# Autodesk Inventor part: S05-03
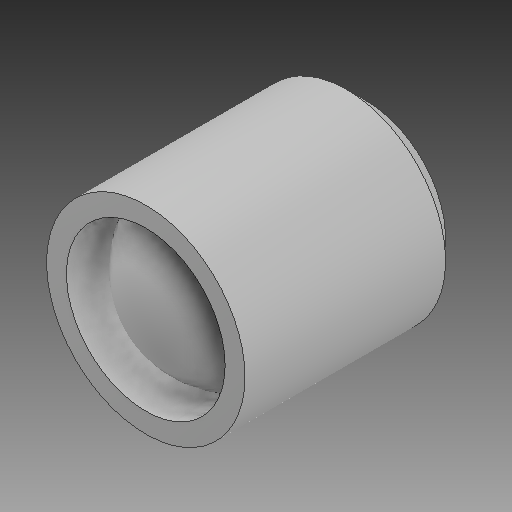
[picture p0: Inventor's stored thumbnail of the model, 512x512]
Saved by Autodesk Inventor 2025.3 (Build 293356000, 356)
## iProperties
Created: 2025-04
Part Number: S05-03
Material: Všeobecné
Document SubType Name: Modeling
Designer: Patrik
Density: 1 g/cm^3
Appearance: Výchozí
Description: Kuličková záslepka
Stock Number: E 2071/ 9
User Status: Ocel
Author: Patrik
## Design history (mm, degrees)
feature "Base1"
node "Těleso1"
